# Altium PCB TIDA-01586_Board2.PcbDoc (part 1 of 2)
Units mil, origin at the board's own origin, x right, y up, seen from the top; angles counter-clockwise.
Board outline 2300 x 1600 mil, 4 copper layers (Layer 1 - Top Layer, Layer 2 - PWR, Layer 3 - GND, Layer 4 - Bottom Layer), stack 61.634 mil thick; 117 components, 50 nets, 280 pads, 152 vias.
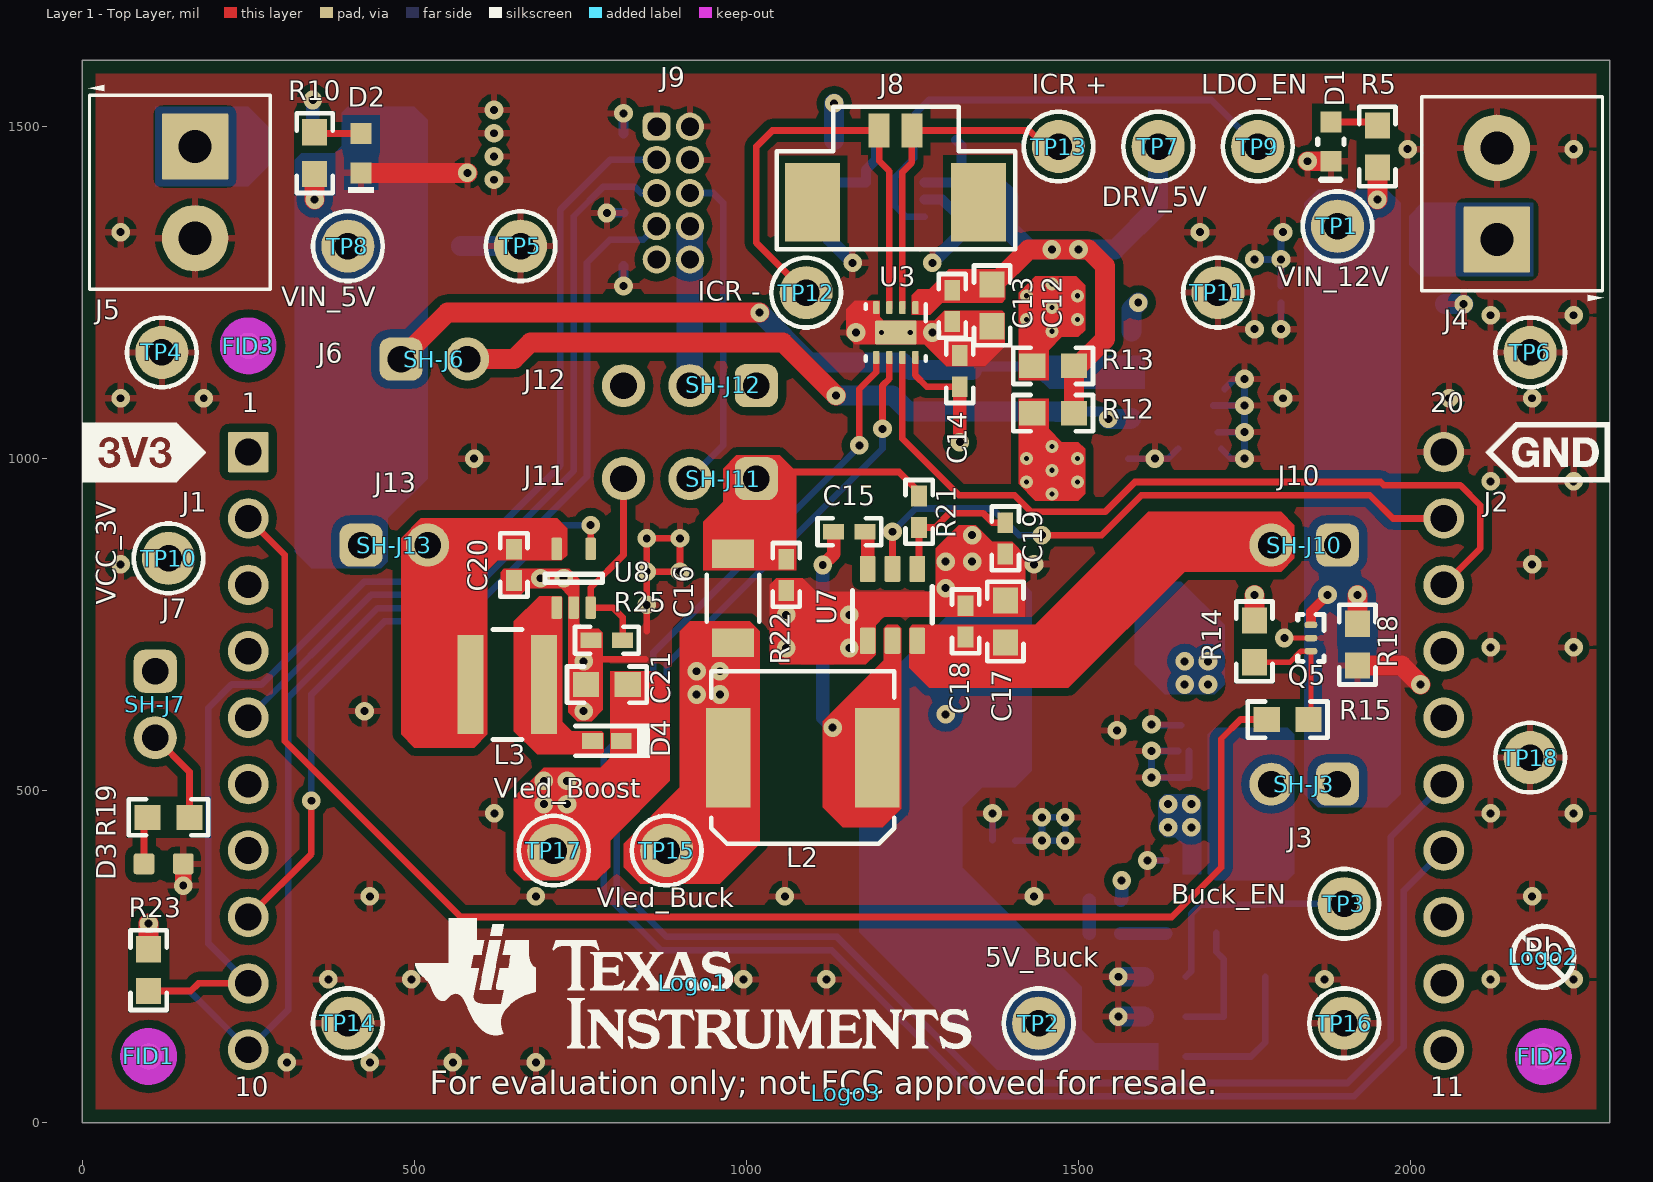
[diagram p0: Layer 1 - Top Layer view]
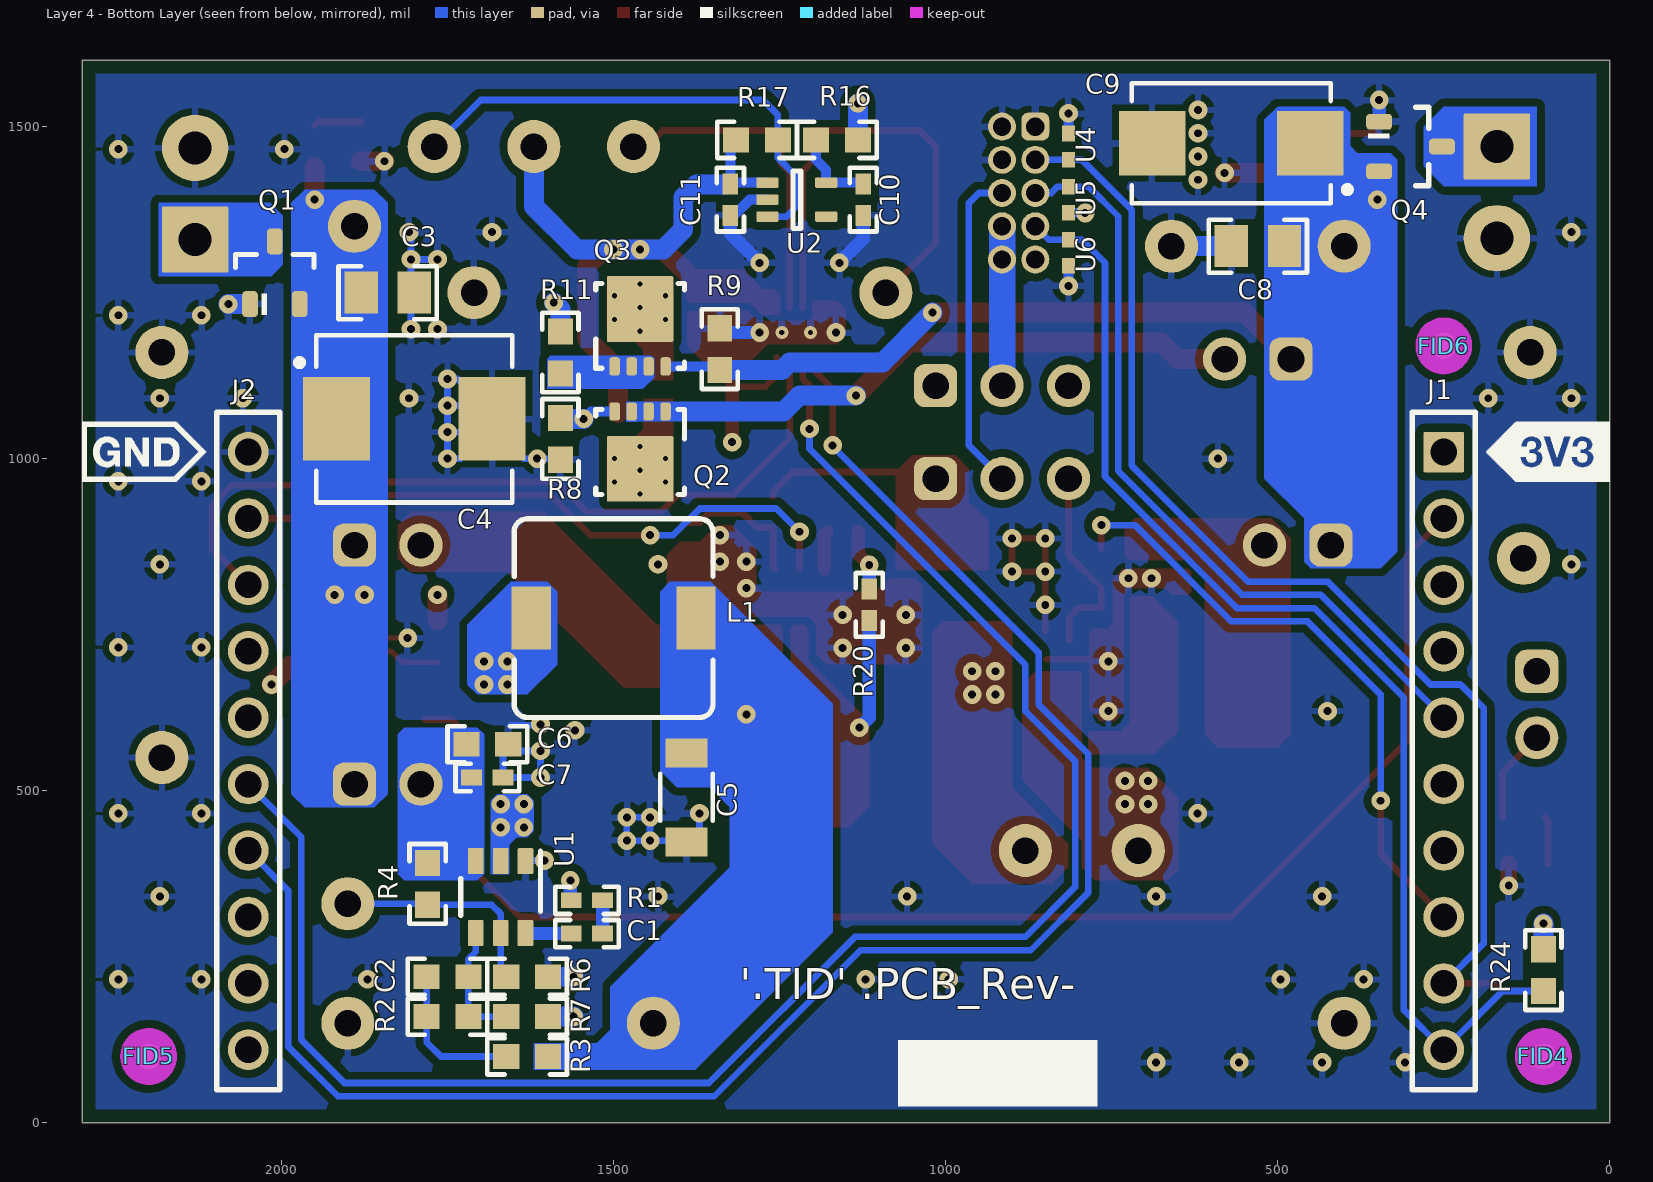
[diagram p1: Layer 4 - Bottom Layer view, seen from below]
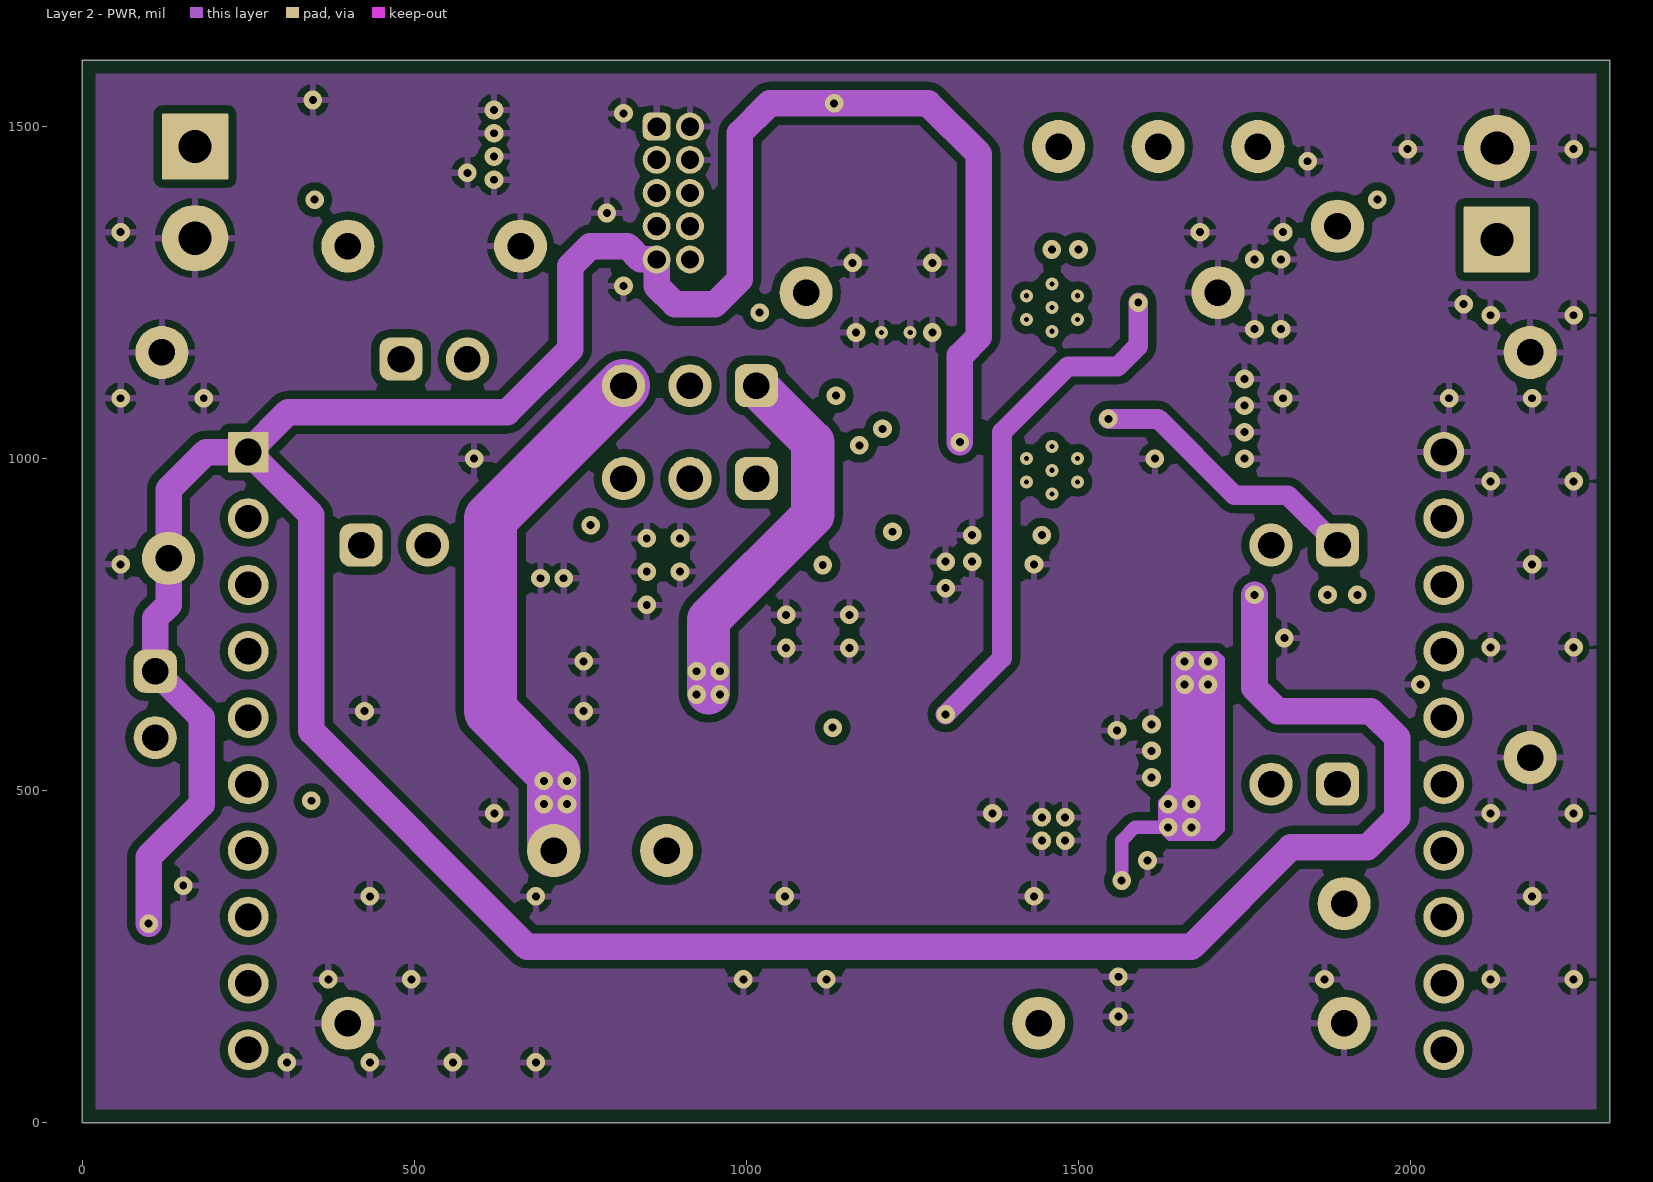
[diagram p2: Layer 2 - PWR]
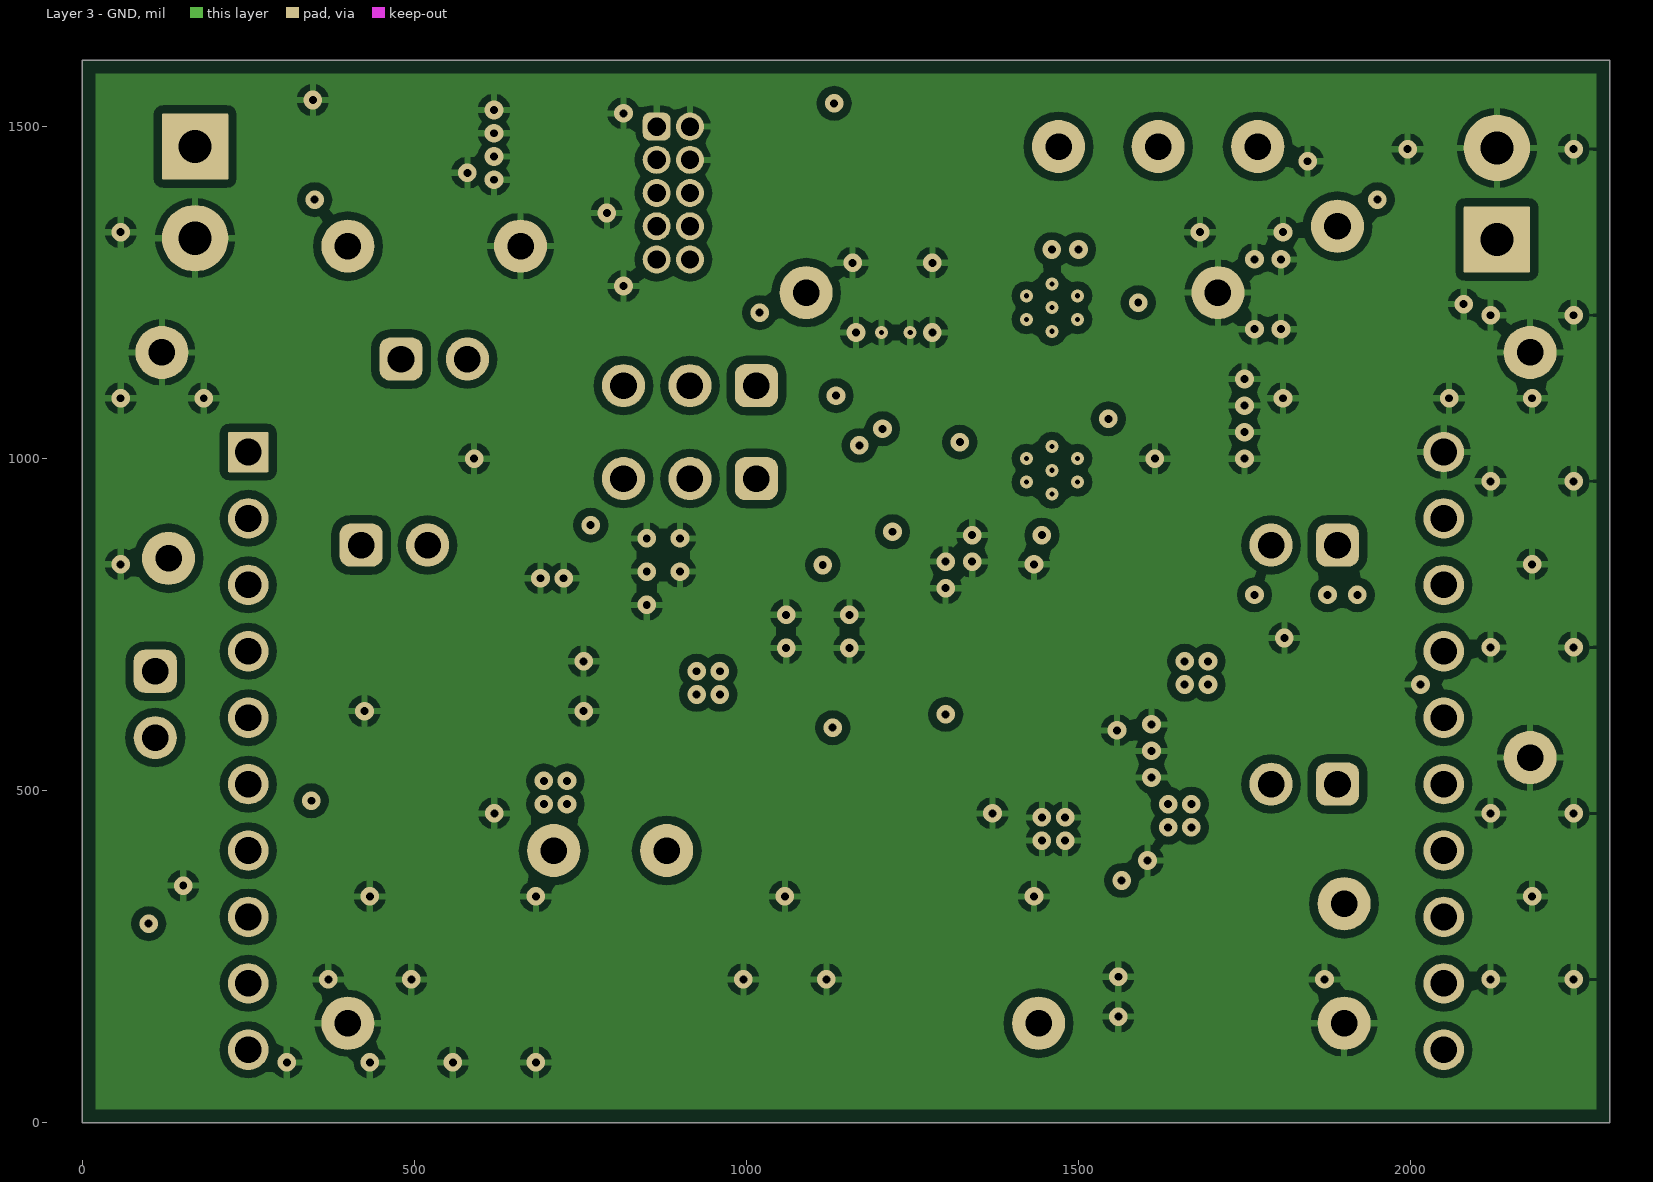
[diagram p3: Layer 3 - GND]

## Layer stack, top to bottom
Top Solder: solder mask 0.4, Solder Resist, Dk 3.5
Layer 1 - Top Layer: signal copper 1.4
Dielectric 1: prepreg 7, FR-4, Dk 4.2
Layer 2 - PWR: signal copper 1.417
Dielectric 2: core 42, FR-4, Dk 4.8
Layer 3 - GND: signal copper 1.417
Dielectric 3: prepreg 7, FR-4, Dk 4.2
Layer 4 - Bottom Layer: signal copper 1.4
Bottom Solder: solder mask 0.4, Solder Resist, Dk 3.5

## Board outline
0,0 0,1600 2300,1600 2300,0

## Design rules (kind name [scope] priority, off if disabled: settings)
AcuteAngle [All] p1: minimum=4.50000000000000E+0001 checktracksonly=FALSE
AssemblyTestPointUsage [All] p1: valid=2
BoardOutlineClearance BoardOutlineClearance_MountingHoles [OnCopper and InComponentClass('Mounting Holes')] p1: gap=40
BoardOutlineClearance BoardOutlineClearance_Poly [OnCopper and IsPoly] p2: gap=20
BoardOutlineClearance [OnCopper and Not InComponentClass('Logo') and not InComponentClass('FiducialMark') and not InRegion(1000,500,4000,800) and not InPoly] p3: gap=35
Clearance Clearance_Keepouts [((IsTrack Or IsArc) And Not InPoly) And IsFree and IsKeepOut vs ((IsTrack Or IsArc) And Not InPoly) And IsFree and IsKeepOut] p1: gap=0
Clearance Clearance_Poly [InPolygon] p2: gap=12
Clearance Clearance_FiducialMark [IsKeepOut and InComponentClass('FiducialMark') vs IsPad and InComponentClass('FiducialMark')] p3: gap=0
Clearance [All] p4: gap=7.87
ComponentClearance ComponentClearance_MountingHoles_FiducialMarks [InComponentClass('Mounting Holes') vs InComponentClass('FiducialMark')] p1: gap=50 collisioncheckmode=3 verticalgap=10 showdistances=FALSE
ComponentClearance ComponentClearance_Shunt [InComponentClass('Header') vs InComponentClass('Shunt')] p2: gap=0 collisioncheckmode=3 verticalgap=0 showdistances=FALSE
ComponentClearance ComponentClearance_Logo [InComponentClass('Logo')] p3: gap=10 collisioncheckmode=3 verticalgap=10 showdistances=TRUE
ComponentClearance ComponentClearance_ScrewToNut [(HasFootprint('NY PMS 440 0025 PH')) vs (HasFootprint('Keystone_1902C'))] p4: gap=5 collisioncheckmode=3 verticalgap=10 showdistances=TRUE
ComponentClearance ComponentClearance_MountingHoles [InComponentClass('Mounting Holes')] p5: gap=250 collisioncheckmode=3 verticalgap=100000 showdistances=TRUE
ComponentClearance ComponentClearance_SmallPassives [HasFootprint('0201*') or HasFootprint('0402*') or HasFootprint('0508') or HasFootprint('0603*') or HasFootprint('0612') or HasFootprint('0805*') or HasFootprint('0815*') or HasFootprint('0830*') or HasFootprint('1206*') or HasFootprint('1210*') or HasFootprint('1808*') or HasFootprint('1812*') or HasFootprint('1825*') or HasFootprint('2010*') or HasFootprint('2220*') or HasFootprint('2225*') or HasFootprint('2512*') or HasFootprint('2728*') or HasFootprint('3518*') vs HasFootprint('0201*') or HasFootprint('0402*') or HasFootprint('0508') or HasFootprint('0603*') or HasFootprint('0612') or HasFootprint('0805*') or HasFootprint('0815*') or HasFootprint('0830*') or HasFootprint('1206*') or HasFootprint('1210*') or HasFootprint('1808*') or HasFootprint('1812*') or HasFootprint('1825*') or HasFootprint('2010*') or HasFootprint('2220*') or HasFootprint('2225*') or HasFootprint('2512*') or HasFootprint('2728*') or HasFootprint('3518*')] p6: gap=10 collisioncheckmode=3 verticalgap=10 showdistances=TRUE
ComponentClearance ComponentClearance_THtoSMT [IsThruComponent vs IsSMTComponent] p7: gap=20 collisioncheckmode=3 verticalgap=30 showdistances=TRUE
ComponentClearance ComponentClearance_THtoTH [IsThruComponent vs IsThruComponent] p8: gap=30 collisioncheckmode=3 verticalgap=30 showdistances=TRUE
ComponentClearance [All] p9: gap=30 collisioncheckmode=3 verticalgap=10 showdistances=FALSE
DiffPairsRouting [All] p1: maxlimit=100 minlimit=10 mostfreqgap=10 toplayer_minwidth=15 toplayer_maxwidth=15 toplayer_prefwidth=15 midlayer1_minwidth=15 midlayer1_maxwidth=15 midlayer1_prefwidth=15 midlayer2_minwidth=15 midlayer2_maxwidth=15 midlayer2_prefwidth=15 bottomlayer_minwidth=15 bottomlayer_maxwidth=15 bottomlayer_prefwidth=15 maxuncoupledlength=1000
FabricationTestPointUsage TestPointUsage [All] p1: valid=2 allowmultiple=FALSE
FabricationTestpoint Testpoint [All] p1: side=3 testpointundercomponent=TRUE minsize=40 maxsize=100 preferedsize=60 minholesize=0 maxholesize=40 preferedholesize=32 testpointgrid=1 allowsidetop=TRUE allowsidebottom=TRUE usegrid=TRUE gridtolerance=0.01
FanoutControl Fanout_LCC [IsLCC] p1: bgadir=Out bgaviamode=Centered fanoutstyle=Auto fanoutdirection=Alternating viagrid=1 // Fanout_LCC (Default Rule)
FanoutControl Fanout_BGA [IsBGA] p2: bgadir=Out bgaviamode=Centered fanoutstyle=Auto fanoutdirection=Alternating viagrid=1 // Fanout_BGA (Default Rule)
FanoutControl Fanout_Default [All] p4: bgadir=Out bgaviamode=Centered fanoutstyle=Auto fanoutdirection=Alternating viagrid=1 // Fanout_Default (Default Rule)
FanoutControl Fanout_Small [(CompPinCount < 5)] p5: bgadir=Out bgaviamode=Centered fanoutstyle=Auto fanoutdirection=OutThenIn viagrid=1 // Fanout_Small (Default Rule)
HoleSize [All] p1: absolutevalues=TRUE maxlimit=251 minlimit=7.87 maxpercent=80.000 minpercent=20.000
MinimumAnnularRing MinimumAnnularRing_ThermalPadVias [IsVia and InAnyComponent] p1: minimumring=5.91
MinimumAnnularRing [All] p2: minimumring=5
MinimumSolderMaskSliver MinimumSolderMaskSliver_Logo [InComponentClass('Logo') vs InComponentClass('Logo')] p1: minsoldermaskwidth=0.7
MinimumSolderMaskSliver [All] p2: minsoldermaskwidth=3.94
PlaneConnect [All] p1: planeconnectstyle=Relief reliefexpansion=10 reliefentries=4 reliefconductorwidth=10 reliefairgap=10
PolygonConnect [All] p1: connectstyle=Relief reliefconductorwidth=10 reliefentries=4 polygonreliefangle="90 Angle" airgapwidth=10
RoutingVias ThermalPadVias [IsVia and InAnyComponent] p1: holewidth=7.87 width=19.68 viastyle="Through Hole" minholewidth=7.87 minwidth=19.68 maxholewidth=12.99 maxwidth=23.62
RoutingVias [All] p2: holewidth=16 width=34 viastyle="Through Hole" minholewidth=7.87 minwidth=26 maxholewidth=40 maxwidth=65
SilkToBoardRegionClearance [Not ((IsComment or IsDesignator) And (Hide <> 'False')) and not InRegion(1000,500,4000,800)] p1:
SilkToSilkClearance SilkToSilkClearance_Pb-FreeLogo [(HasFootprint('Pb-Free_Overlay_Medium') OR HasFootprint('Pb-Free_Overlay_Small')) vs (HasFootprint('Pb-Free_Overlay_Medium') OR HasFootprint('Pb-Free_Overlay_Small'))] p1: silktosilkclearance=0
SilkToSilkClearance [All] p2: silktosilkclearance=4
SilkToSolderMaskClearance SilkToComponentPadClearance [(IsPad or IsFill or IsRegion) and InAnycomponent] p1: minsilkscreentomaskgap=3.8 clearancetoexposedcopper=TRUE
SilkToSolderMaskClearance "Silk to Solder Mask Opening" [All] p2: minsilkscreentomaskgap=5 clearancetoexposedcopper=FALSE
SolderMaskExpansion [All] p1: expansion=1.97
Width [All] p1: maxlimit=100 minlimit=6 preferedwidth=10 checkconnectedcopper=TRUE
15 further rules are at their usual default settings.

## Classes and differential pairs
component class Logo: Logo1
component class TIDA-01586_Board2_Hardware: FID1 FID2 FID3 FID4 FID5 FID6 Logo1 Logo2 Logo3 SH-J3 SH-J6 SH-J7 SH-J10 SH-J11 SH-J12 SH-J13 ZZ1 ZZ2 ZZ3 ZZ4
component class FiducialMark: FID1 FID2 FID3 FID4 FID5 FID6
component class AssemblyNote: ZZ1 ZZ2 ZZ3 ZZ4
component class Header: J3 J6 J7 J9 J10 J11 J12 J13
component class Shunt: SH-J3 SH-J6 SH-J7 SH-J10 SH-J11 SH-J12 SH-J13
component class TIDA-01586_Board2_MCU_Drivers: C12 C13 C14 C15 C16 C17 C18 C19 C20 C21 D4 J1 J2 J8 J9 J10 J11 J12 J13 L2 L3 R20 R21 R22 R23 R24 R25 TP12 TP13 TP14 TP15 TP16 TP17 TP18 U3 U4 U5 U6 U7 U8
component class TIDA-01586_Board2_Power: C1 C2 C3 C4 C5 C6 C7 C8 C9 C10 C11 D1 D2 D3 J3 J4 J5 J6 J7 L1 Q1 Q2 Q3 Q4 Q5 R1 R2 R3 R4 R5 R6 R7 R8 R9 R10 R11 R12 R13 R14 R15 R16 R17 R18 R19 TP1 TP2 TP3 TP4 TP5 TP6 TP7 TP8 TP9 TP10 TP11 U1 U2

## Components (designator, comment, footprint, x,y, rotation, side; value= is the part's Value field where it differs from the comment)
C1 "GRM155R71A104KA01D" 0402 1540,285 r180 bottom
C2 "GRM1885C1H101JA01D" 0603 1750,220 r180 bottom
C3 "C0805C105K3RACTU" 0805_HV 1840,1250 r180 bottom
C4 "TPSV107K025R0100" 7361-38 1800,1060 r180 bottom
C5 "GRT31CR61A476KE13L" 1206_180 1390,490 r270 bottom
C6 "GRM188R61E106MA73D" 0603 1690,570 r180 bottom
C7 "C1005X7R1H104K050BB" 0402 1690,520 r180 bottom
C8 "C0805C105K3RACTU" 0805_HV 530,1320 r180 bottom
C9 "TPSD107K010R0100" 7343-31 570,1475 r0 bottom
C10 "GRM155R61A105ME15D" 0402 1124.09,1390 r90 bottom
C11 "GRM155R61A105ME15D" 0402 1324.09,1390 r270 bottom
C12 "GRM188R61E106MA73D" 0603 1370,1231 r270 top
C13 "GRM155R71A104KA01D" 0402 1310,1230 r270 top
C14 "GRM155R71A104KA01D" 0402 1321.32,1131.95 r90 top
C15 "GRM155R71A104KA01D" 0402 1155,890 r180 top
C16 "C3216X5R1E336M160AC" 1206_180 980,790 r90 top
C17 "GRM188R61E106MA73D" 0603 1390,755 r90 top
C18 "C1005X7R1H104K050BB" 0402 1330,755 r90 top
C19 "GRM155R71A823KA01D" 0402 1390,880 r270 top
C20 "CL05A106MP5NUNC" 0402 650,840 r270 top
C21 "GRM188R6YA475KE15D" 0603 790,660 r180 top
D1 "LS L29K-G1J2-1-Z" "LS L29K_Red" 1880,1477.38 r270 top
D2 "LB Q39G-L2N2-35-1" "LB Q39G_BLUE" 420,1460 r270 top
D3 "LP L296-J2L2-25" LPL296_Green 122.62,390 r0 top
D4 "NSR0240V2T1G" SOD-523 790,575 r180 top
FID1 "Fiducial" Fiducial10-20 100,100 r0 top
FID2 "Fiducial" Fiducial10-20 2200,100 r0 top
FID3 "Fiducial" Fiducial10-20 250,1170 r0 top
FID4 "Fiducial" Fiducial10-20 100,100 r180 bottom
FID5 "Fiducial" Fiducial10-20 2200,100 r180 bottom
FID6 "Fiducial" Fiducial10-20 250,1170 r180 bottom
J1 "SSQ-110-03-F-S" BoosterPack_20pin_J1 250,560 r180 bottom
J2 "SSQ-110-03-F-S" BoosterPack_20pin_J2 2050,560 r180 bottom
J3 "TSW-102-07-G-S" TSW-102-07-G-S 1840,510 r180 top
J4 "ED555/2DS" TERM_BLK_ED555-2DS 2130,1330 r90 top
J5 "ED555/2DS" TERM_BLK_ED555-2DS 170,1470 r270 top
J6 "TSW-102-07-G-S" TSW-102-07-G-S 530,1150 r0 top
J7 "TSW-102-07-G-S" TSW-102-07-G-S 110,630 r270 top
J8 "53398-0271" 0533980271 1224.6,1440 r0 top
J9 "GRPB052VWVN-RC" CONN_GRPB052VWVN-RC 890,1400 r270 top
J10 "TSW-102-07-G-S" TSW-102-07-G-S 1840,870 r180 top
J11 "TSW-103-07-G-S" TSW-103-07-G-S 915,970 r180 top
J12 "TSW-103-07-G-S" TSW-103-07-G-S 915,1110 r180 top
J13 "TSW-102-07-G-S" TSW-102-07-G-S 470,870 r0 top
L1 "SRR0745A-220M" SRR0745A 1500,760 r180 bottom
L2 "ELL-6UH181M" ELL6UH 1085,550 r180 top
L3 "IFSC1515AHER4R7M01" IFSC1515AH 640,660 r0 top
Logo1 "Texas Instruments" TI_Stacked_Overlay_Small 920,210 r0 top
Logo2 "Pb-Free Symbol" Pb-Free_Overlay_Small 2200,250 r0 top
Logo3 "FCC disclaimer" FCC_disclaimer 1150,45 r0 top
Q1 "SI2343CDS-T1-GE3" SOT-23 2010,1280 r90 bottom
Q2 "CSD25402Q3A" DNH0008A 1460,1010 r270 bottom
Q3 "CSD25402Q3A" DNH0008A 1460,1200 r90 bottom
Q4 "SI2343CDS-T1-GE3" SOT-23 300,1470 r180 bottom
Q5 "CSD17585F5T" YJK0003A 1850,730 r270 top
R1 "RC0402JR-070RL" 0402 1540,335 r0 bottom
R2 "RC0603FR-07100KL" 0603 1750,160 r180 bottom
R3 "RC0603JR-070RL" 0603 1630,100 r0 bottom
R4 "RC0603FR-07154KL" 0603 1780,360 r270 bottom
R5 "CRCW06032K87FKEA" 0603 1950,1470 r270 top
R6 "RC0603FR-0719K6L" 0603 1630,220 r0 bottom
R7 "RC0603FR-0713K3L" 0603 1630,160 r0 bottom
R8 "RC0603JR-0747KL" 0603 1580,1030 r90 bottom
R9 "RC0603JR-0747KL" 0603 1340,1165 r270 bottom
R10 "CRCW0603590RFKEA" 0603 350,1460 r270 top
R11 "RC0603JR-070RL" 0603 1580,1160 r90 bottom
R12 "RC0603JR-070RL" 0603 1462,1068.54 r0 top
R13 "RC0603JR-070RL" 0603 1462,1139.84 r180 top
R14 "RC0603FR-0710KL" 0603 1765,725 r90 top
R15 "RC0603JR-070RL" 0603 1815,607.24 r180 top
R16 "RC0603JR-070RL" 0603 1163.58,1480 r180 bottom
R17 "RC0603JR-070RL" 0603 1284.09,1480 r180 bottom
R18 "RC0603JR-0747KL" 0603 1920,720 r270 top
R19 "CRCW0603487RFKEA" 0603 130,460 r0 top
R20 "RC0402JR-070RL" 0402 1115,780 r270 bottom
R21 "CRCW0402910RJNED" 0402 1260,920 r90 top
R22 "CRCW04027R87FKED" 0402 1060,825 r90 top
R23 "RC0603FR-0710KL" 0603 100,230 r90 top
R24 "RC0603FR-0710KL" 0603 100,230 r90 bottom
R25 "CRCW04027R87FKED" 0402 790,726.7 r0 top
SH-J3 "SNT-100-BK-G" SNT-100-BK-G 1840,510 r180 top
SH-J6 "SNT-100-BK-G" SNT-100-BK-G 530,1150 r180 top
SH-J7 "SNT-100-BK-G" SNT-100-BK-G 110,630 r90 top
SH-J10 "SNT-100-BK-G" SNT-100-BK-G 1840,870 r180 top
SH-J11 "SNT-100-BK-G" SNT-100-BK-G 965,970 r180 top
SH-J12 "SNT-100-BK-G" SNT-100-BK-G 965,1111.25 r180 top
SH-J13 "SNT-100-BK-G" SNT-100-BK-G 470,870 r180 top
TP1 "5000" Keystone5000 1890,1350 r90 top
TP2 "5000" Keystone5000 1440,150 r90 top
TP3 "5004" Keystone5004 1900,330 r90 top
TP4 "5001" Keystone5001 120,1160 r90 top
TP5 "5001" Keystone5001 660,1320 r90 top
TP6 "5001" Keystone5001 2180,1160 r90 top
TP7 "5002" Keystone5002 1620,1470 r0 top
TP8 "5000" Keystone5000 400,1320 r90 top
TP9 "5004" Keystone5004 1770,1470 r0 top
TP10 "5000" Keystone5000 130,850 r90 top
TP11 "5001" Keystone5001 1710,1250 r90 top
TP12 "5002" Keystone5002 1090,1250 r90 top
TP13 "5002" Keystone5002 1470,1470 r0 top
TP14 "5001" Keystone5001 400,150 r90 top
TP15 "5000" Keystone5000 880,410 r90 top
TP16 "5001" Keystone5001 1900,150 r90 top
TP17 "5000" Keystone5000 710,410 r90 top
TP18 "5001" Keystone5001 2180,550 r90 top
U1 "TPS54202DDCR" DDC0006A_N 1670,340 r270 bottom
U2 "TLV70033DCKR" DCK0005A_N 1224.09,1390 r180 bottom
U3 "DRV8837CDSG" DSG0008A 1225,1190 r270 top
U4 "TPD1E10B06DPYR" DPY0002A 815,1470 r90 bottom
U5 "TPD1E10B06DPYR" DPY0002A 815,1390 r270 bottom
U6 "TPD1E10B06DPYR" DPY0002A 815,1310 r270 bottom
U7 "TPS54201DDCR" DDC0006A_N 1220,780 r90 top
U8 "TPS61169DCKR" DCK0005A_N 740,820 r90 top
ZZ1 "This Assembly Note is for PCB labels only" AssemblyNoteLabel 100,2000 r0 top
ZZ2 "These assemblies are ESD sensitive, ESD precautions shall be observed." AssemblyNote 100,1900 r0 top
ZZ3 "These assemblies must be clean and free from flux and all contaminants. Use of no clean flux is not acceptable." AssemblyNote 100,1800 r0 top
ZZ4 "These assemblies must comply with workmanship standards IPC-A-610 Class 2, unless otherwise specified." AssemblyNote 100,1700 r0 top

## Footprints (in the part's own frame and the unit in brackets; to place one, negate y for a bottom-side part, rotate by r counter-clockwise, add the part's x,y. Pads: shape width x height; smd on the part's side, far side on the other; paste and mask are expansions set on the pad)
0402 [mm] "0402 from SM-752 data"
  rect 0.8x0.6 smd: 1(-0.6,0) 2(0.6,0)
  silkscreen extent -1.22,-0.52 1.22,0.52, body extent -0.55,-0.3 0.55,0.3, height 0.6
0603 [mm] "0603 from SM-752 data"
  rect 1x0.95 smd: 1(-0.8,0) 2(0.8,0)
  silkscreen extent -1.52,-0.69 1.52,0.69, body extent -0.87,-0.47 0.87,0.47, height 1
0805_HV [mil] "0805 with 30mil clearance between pads"
  rect 50x63 smd: 1(-40,0) 2(40,0)
  silkscreen extent -74,-40 74,40, body extent -43,-29 43,29, height 57
1206_180 [mm] "1206_180"
  rect 1.1x1.6 smd: 1(-1.7,0) 2(1.7,0)
  silkscreen extent -0.9,-1 0.9,1, body extent -1.75,-0.95 1.75,0.95, height 1.8
7343-31 [mm] "Medium Density based on Kemet T495 dimensions"
  rect 2.55x2.45 smd: 1(-3.025,0) 2(3.025,0)
  silkscreen extent -4.56,-2.3 3.8,2.3, body extent -3.8,-2.3 3.8,2.3, height 3.1
7361-38 [mm] "Medium density IPC based on AVX dimensions for TPS series"
  rect 2.55x3.2 smd: 1(-2.975,0) 2(2.975,0)
  silkscreen extent -4.51,-3.2 3.75,3.2, body extent -3.75,-3.15 3.75,3.15, height 3.8
0533980271 [mm] "Molex PicoBlade 2 pos from documents no. SD-53398-033 dated 2006-04-02"
  rect 0.8x1.3 smd: 1(-0.625,1.375) 2(0.625,1.375)
  rect 2.1x3 smd: 3(-3.175,-1.375) 4(3.175,-1.375)
  silkscreen extent -4.55,-3.17 4.57,2.29, body extent -3.86,-2.44 3.79,1.76, height 4.8
AssemblyNote [mil] "Assembly Note"
AssemblyNoteLabel [mil] "Assembly Note for PCB Labels"
BoosterPack_20pin_J1 [mm] "Receptacle, 2.54mm, 10x1, TH"
  rrect6% 1.55x1.55 hole 1.02: 1(0,11.43)
  round 1.55 hole 1.02: 2(0,8.89) 3(0,6.35) 4(0,3.81) 5(0,1.27) 6(0,-1.27) 7(0,-3.81) 8(0,-6.35) 9(0,-8.89) 10(0,-11.43)
  silkscreen extent -1.21,-12.95 6.35,12.95, body extent -1.21,-12.95 1.21,12.95, height 8.51
BoosterPack_20pin_J2 [mm] "Receptacle, 2.54mm, 10x1, TH"
  round 1.55 hole 1.02: 11(0,-11.43) 12(0,-8.89) 13(0,-6.35) 14(0,-3.81) 15(0,-1.27) 16(0,1.27) 17(0,3.81) 18(0,6.35) 19(0,8.89) 20(0,11.43)
  silkscreen extent -6.35,-12.95 1.21,12.95, body extent -1.21,-12.95 1.21,12.95, height 8.51
CONN_GRPB052VWVN-RC [mm] "SULLINS"
  rrect50% 1.07x1.07 hole 0.7: 1(-2.54,-0.635)
  round 1.07 hole 0.7: 2(-2.54,0.635) 3(-1.27,-0.635) 4(-1.27,0.635) 5(0,-0.635) 6(0,0.635) 7(1.27,-0.635) 8(1.27,0.635) 9(2.54,-0.635) 10(2.54,0.635)
  body extent -3.17,-1.7 3.17,1.7, height 4
DCK0005A_N [mm] "SOT353, 5-Leads, Body 2x1.3mm, Pitch 0.65mm, Lead Span 2.1mm, IPC Medium Density"
  rrect25% 0.85x0.4 smd: 1(-1.125,0.65) 2(-1.125,0) 3(-1.125,-0.65) 4(1.125,-0.65) 5(1.125,0.65)
  silkscreen extent -0.15,-1.1 0.15,1.1, body extent -1.14,-1 1.14,1, height 0.95
DDC0006A_N [mm]
  rrect17% 1x0.6 smd: 1(-1.375,0.95) 2(-1.375,0) 3(-1.375,-0.95) 4(1.375,-0.95) 5(1.375,0) 6(1.375,0.95)
  silkscreen extent -1.75,-1.52 0.7,1.53, body extent -1.43,-1.48 1.43,1.49, height 0.92
DNH0008A [mm] "8 pin VSONP, 0.65 mm pitch"
  rrect50% 0.7x0.4 smd paste-0.05 mask-0.05: 1(-1.55,0.975) 2(-1.55,0.325) 3(-1.55,-0.325) 4(-1.55,-0.975) 5(1.55,-0.975) 6(1.55,-0.325) 7(1.55,0.325) 8(1.55,0.975)
  rrect14% 0.705x1.125 on Bottom Paste: 9(-0.208,-0.663) 9(-0.208,0.662) 9(0.697,-0.663) 9(0.697,0.662)
  rrect6% 1.775x2.45 on Bottom Solder: 9(0.327,0)
  rrect4% 2.51x2.55 smd paste-1.5 mask-1.5: 9(0.645,0)
  rect 0.5x0.3 on Bottom Solder: 9(1.175,-0.975) 9(1.175,-0.325) 9(1.175,0.325) 9(1.175,0.975)
  silkscreen extent -1.62,-1.7 1.62,1.7, body extent -1.65,-1.65 1.65,1.66, height 0.91
DPY0002A [mm] "R-PX2SON-N2"
  rect 0.6x0.5 smd: 1(-0.5,0) 2(0.5,0)
  body extent -0.55,-0.35 0.55,0.35, height 0.4
DSG0008A [mm] "SON, 8-Leads, Body 2x2mm, Pitch 0.5mm, Thermal Pad 1.6x0.9mm, TI Recommended"
  rrect40% 0.5x0.25 smd: 1(-0.95,0.75) 2(-0.95,0.25) 3(-0.95,-0.25) 4(-0.95,-0.75) 5(0.95,-0.75) 6(0.95,-0.25) 7(0.95,0.25) 8(0.95,0.75)
  rrect14% 0.9x0.7 on Top Paste: 9(0,0.45) 9(0,-0.45)
  rrect11% 0.9x1.6 smd paste-0.45: 9(0,0)
  silkscreen extent -1.07,-1.15 1.07,1.15, body extent -1,-1 1,1, height 0.77
ELL6UH [mm] "Panasonic recommended land pattern"
  rect 1.7x3.8 smd: 1(-2.85,0) 2(2.85,0)
  silkscreen extent -3.5,-3.3 3.5,3.3, body extent -3.45,-3.25 3.45,3.25, height 5
FCC_disclaimer [mil]
Fiducial10-20 [mm]
  round 1 smd mask+0.5: 1(0,0)
  Layer 1 - Top Layer keep-out circle w1.178: c0,0 r0.5
IFSC1515AH [mm] "SMD, 2-Leads, Body 3.8x3.8mm"
  rect 1x3.8 smd: 1(-1.4,0) 2(1.4,0)
  silkscreen extent -0.55,-2.1 0.55,2.1, body extent -2,-2 2,2, height 1.9
Keystone5000 [mil] "For Keystone 500x miniature loop terminals"
  round 80 hole 40: 1(0,0)
  silkscreen extent -52,-52 52,52, body extent -49,-49 49,49, height 182
Keystone5001 [mil] "For Keystone 500x miniature loop terminals"
  round 80 hole 40: 1(0,0)
  silkscreen extent -52,-52 52,52, body extent -49,-49 49,49, height 182
Keystone5002 [mil] "For Keystone 500x miniature loop terminals"
  round 80 hole 40: 1(0,0)
  silkscreen extent -52,-52 52,52, body extent -49,-49 49,49, height 182
Keystone5004 [mil] "For Keystone 500x miniature loop terminals"
  round 80 hole 40: 1(0,0)
  silkscreen extent -52,-52 52,52, body extent -49,-49 49,49, height 182
"LB Q39G_BLUE" [mm] "OSRAM"
  rect 0.8x0.8 smd: 1(-0.75,0) 2(0.75,0)
  silkscreen extent 1.3,-0.5 1.52,0.5, body extent -0.85,-0.45 0.85,0.45, height 0.4
LPL296_Green [mm] "SMD, 2-Leads, Body 1.3x0.8mm"
  rrect25% 0.8x0.8 smd paste-1: 1(-0.75,0) 2(0.75,0)
  rrect17% 0.6x0.7 on Top Paste mask-1: ""(-0.8,0) ""(0.8,0)
  body extent -0.9,-0.45 0.9,0.45, height 0.67
"LS L29K_Red" [mm] "SMD, 2-Leads, Body 1.3x0.8mm"
  rect 0.8x0.8 smd paste-0.4: 1(-0.75,0) 2(0.75,0)
  silkscreen extent -0.1,-0.5 1.45,0.5, body extent -0.9,-0.45 0.9,0.45, height 0.67
Pb-Free_Overlay_Small [mil]
  silkscreen extent -46,-46 46,46
SNT-100-BK-G [mil] "Samtec STEP model"
  round 1 on Mech3: 0(0,0)
  body extent -100,-50 100,50, height 344
SOD-523 [mm] "NXP Semiconductor recommended land pattern, nominal STEP model"
  rect 0.8x0.6 smd paste-0.05: 1(-0.55,0) 2(0.55,0)
  silkscreen extent -1.65,-0.66 1.2,0.66, body extent -0.8,-0.4 0.8,0.4, height 0.72
SOT-23 [mm] "SOT23, 3-Leads, Body 2.9x1.3mm, Pitch 0.95mm, Lead Span 2.5mm, IPC Medium Density"
  rrect50% 1x0.6 smd: 1(-1.2,0.95) 2(-1.2,-0.95) 3(1.2,0)
  silkscreen extent -1.62,-1.5 0.7,1.5, body extent -1.16,-1.45 1.21,1.45, height 1
SRR0745A [mm] "BOURNS"
  rect 1.5x2.4 smd: 1(-3.15,0) 2(3.15,0)
  silkscreen extent -3.8,-3.8 3.8,3.8, body extent -3.75,-3.75 3.75,3.75, height 4.7
TERM_BLK_ED555-2DS [mil]
  rrect4% 100x100 hole 50: 1(0,0)
  round 100 hole 50: 2(138,0)
  silkscreen extent -93,-161 215,113, body extent -69,-150 207,106, height 323
TI_Stacked_Overlay_Small [mil]
  silkscreen extent -418,-98 418,98
TSW-102-07-G-S [mm] "Samtec 100mil, 1x2, 230 mil above insulator"
  rrect50% 1.65x1.65 hole 1.016: 1(-1.27,0)
  round 1.65 hole 1.016: 2(1.27,0)
  body extent -2.54,-1.27 2.54,1.27, height 8.38
TSW-103-07-G-S [mm] "Samtec 100mil, 1x3, 230 mil above insulator"
  rrect50% 1.65x1.65 hole 1.016: 1(-2.54,0)
  round 1.65 hole 1.016: 2(0,0) 3(2.54,0)
  body extent -3.81,-1.27 3.81,1.27, height 8.38
YJK0003A [mm] "SMD, 3-Leads, Body 1.49x0.73mm"
  rrect50% 0.2x0.39 on Top Paste: 1(-0.525,0) 2(0,0) 3(0.525,0)
  rrect80% 0.25x0.49 smd paste-0.15 mask-0.05: 1(-0.5,0) 2(0,0) 3(0.5,0)
  silkscreen extent -0.9,-0.5 0.9,0.5, body extent -0.75,-0.37 0.74,0.36, height 0.35

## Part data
C1 C13 C14 C15: library part CMP-0006629-2, "CAP, CERM, 0.1 uF, 10 V, +/- 10%, X7R, 0402"
C2: library part CMP-0007171-4, "CAP, CERM, 100 pF, 50 V, +/- 5%, C0G/NP0, 0603"
C3 C8: library part CMP-0007728-2, "CAP, CERM, 1 uF, 25 V, +/- 10%, X7R, 0805"
C4: library part CMP-0012041-2, "CAP, TA, 100 uF, 25 V, +/- 10%, 0.1 ohm, SMD"
C5: library part CMP-0009013-2, "CAP, CERM, 47 uF, 10 V, +/- 10%, X5R, AEC-Q200 Grade 1, 1206"
C6 C12 C17: library part CMP-0007344-5, "CAP, CERM, 10 uF, 25 V, +/- 20%, X5R, 0603"
C7 C18: library part CMP-0006297-2, "CAP, CERM, 0.1 uF, 50 V, +/- 10%, X7R, 0402"
C9: library part CMP-0011859-2, "CAP, TA, 100 uF, 10 V, +/- 10%, 0.1 ohm, SMD"
C10 C11: library part CMP-0064927-2, "CAP, CERM, 1 uF, 10 V,+/- 20%, X5R, 0402"
C16: library part CMP-0008655-2, "CAP, CERM, 33 uF, 25 V, +/- 20%, X5R, 1206"
C19: library part CMP-0006637-2, "CAP, CERM, 0.082 uF, 10 V, +/- 10%, X7R, 0402"
C20: library part CMP-0006339-2, "CAP, CERM, 10 uF, 10 V, +/- 20%, X5R, 0402"
C21: library part CMP-0007357-5, "CAP, CERM, 4.7 uF, 35 V, +/- 10%, X5R, 0603"
D1: library part CMP-0002902-1, "LED, Red, SMD"
D2: library part CMP-0002849-1, "LED, Blue, SMD"
D3: library part CMP-0077694-1, "LED, Green, SMD"
D4: library part CMP-0028616-2, "Diode, Schottky, 40 V, 0.25 A, SOD-523"
FID1 FID2 FID3: library part CMP-0077181-1, "Fiducial mark.  There is nothing to buy or mount."
FID4 FID5 FID6: "Fiducial mark.  There is nothing to buy or mount."
J1: library part CMP-0003839-1, "Receptacle, 2.54mm, 10x1, Gold, TH"
J2: library part CMP-0078267-1, "Receptacle, 2.54mm, 10x1, Gold, TH"
J3 J6 J7 J10 J13: library part CMP-0075405-2, "Header, 100mil, 2x1, Gold, TH"
J4 J5: library part CMP-0074913-1, "Terminal Block, 3.5mm Pitch, 2x1, TH"
J8: library part CMP-0055117-1, "Plug, SMT, Vertical, 1.25mm, 1x2"
J9: library part CMP-0002340-2, "Header, 50mil, 5x2, Gold, TH"
J11 J12: library part CMP-0075407-2, "Header, 100mil, 3x1, Gold, TH"
L1: library part CMP-0057729-2, "Inductor, Shielded Drum Core, Ferrite, 22 uH, 1.65 A, 0.096 ohm, AEC-Q200 Grade 1, SMD"
L2: library part CMP-0060108-1, "Inductor, Shielded Drum Core, Ferrite, 180 uH, 0.47 A, 0.75 ohm, SMD"
L3: library part CMP-0063230-1, "Inductor, Shielded, Ferrite, 4.7 uH, 2 A, 0.09 ohm, SMD"
Logo1: library part CMP-0074838-1, "Texas Instrument Corporate Signature"
Logo2: library part CMP-0074839-1
Logo3: library part CMP-0074847-1, "FCC_disclaimer"
Q1 Q4: library part CMP-0000096-2, "MOSFET, P-CH, -30 V, -5.9 A, SOT-23"
Q2 Q3: library part CMP-0000025-2, "MOSFET, P-CH, -20 V, -15 A, DNH0008A (VSONP-8)"
Q5: library part CMP-0067551-1, "MOSFET, N-CH, 30 V, 5.9 A, YJK0003A (PICOSTAR-3)"
R1 R20: library part CMP-0027004-2, "RES, 0, 5%, 0.063 W, 0402"
R2: library part CMP-0022735-3, "RES, 100 k, 1%, 0.1 W, 0603"
R3 R11 R12 R13 R15 R16 R17: library part CMP-0025885-3, "RES, 0, 5%, 0.1 W, 0603"
R4: library part CMP-0022810-2, "RES, 154 k, 1%, 0.1 W, 0603"
R5: library part CMP-0022283-4, "RES, 2.87 k, 1%, 0.1 W, AEC-Q200 Grade 0, 0603"
R6: library part CMP-0022861-3, "RES, 19.6 k, 1%, 0.1 W, 0603"
R7: library part CMP-0022790-3, "RES, 13.3 k, 1%, 0.1 W, 0603"
R8 R9 R18: library part CMP-0025925-3, "RES, 47 k, 5%, 0.1 W, 0603"
R10: library part CMP-0022506-5, "RES, 590, 1%, 0.1 W, AEC-Q200 Grade 0, 0603"
R14 R23 R24: library part CMP-0022746-3, "RES, 10.0 k, 1%, 0.1 W, 0603"
R19: library part CMP-0022442-5, "RES, 487, 1%, 0.1 W, AEC-Q200 Grade 0, 0603"
R21: library part CMP-0026986-3, "RES, 910, 5%, 0.063 W, AEC-Q200 Grade 0, 0402"
R22 R25: library part CMP-0026567-2, "RES, 7.87, 1%, 0.063 W, AEC-Q200 Grade 0, 0402"
SH-J3 SH-J6 SH-J7 SH-J10 SH-J11 SH-J12 SH-J13: library part CMP-0003623-1, "Shunt, 100mil, Gold plated, Black"
TP1 TP2 TP8 TP10 TP15 TP17: library part CMP-0055137-1, "Test Point, Miniature, Red, TH"
TP3 TP9: library part CMP-0055141-1, "Test Point, Miniature, Yellow, TH"
TP4 TP5 TP6 TP11 TP14 TP16 TP18: library part CMP-0055138-1, "Test Point, Miniature, Black, TH"
TP7 TP12 TP13: library part CMP-0055139-1, "Test Point, Miniature, White, TH"
U1: library part CMP-0073969-2, "4.5V to 28V Input, 2A Output, EMI Friendly Synchronous Step-Down Converter, DDC0006A (SOT-23-T-6)"
U2: library part CMP-0035682-1, "Single Output LDO, 200 mA, Fixed 3.3 V Output, 2 to 5.5 V Input, with Low IQ, 5-pin SC70 (DCK), -40 to 125 degC, Green (RoHS & no Sb/Br)"
U3: library part CMP-0013449-3, "1-A Low-Voltage H-Bridge Driver, DSG0008A (WSON-8)"
U4 U5 U6: library part CMP-0043093-1, "ESD in 0402 Package with 10 pF Capacitance and 6 V Breakdown, 1 Channel, -40 to +125 degC, 2-pin X2SON (DPY), Green (RoHS & no Sb/Br)"
U7: library part CMP-0013279-3, "4.5V TO 28V INPUT VOLTAGE, 1.5A OUTPUT CURRENT, SYNCHRONOUS BUCK WLED Driver, DDC0006A (SOT-6)"
U8: library part CMP-0073719-1, "TPS61169 38-V High-Current Boost WLED Driver, DCK0005A (SOT-SC70-5)"
ZZ1: library part CMP-0003616-3
ZZ2: library part CMP-0077236-1
ZZ3: library part CMP-0077237-1
ZZ4: library part CMP-0077238-1

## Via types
v1: diameter 28, hole 12, Layer 1 - Top Layer to Layer 4 - Bottom Layer, tented both sides, 136 vias
v2: diameter 19.68, hole 7.87, Layer 1 - Top Layer to Layer 4 - Bottom Layer, tented both sides, 16 vias

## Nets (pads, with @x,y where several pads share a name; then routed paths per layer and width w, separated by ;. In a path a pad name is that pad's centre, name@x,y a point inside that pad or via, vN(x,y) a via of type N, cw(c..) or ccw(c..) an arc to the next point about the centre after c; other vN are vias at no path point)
5v_buck: C5.1 L1.2 R3.1 R11.2 TP2.1 | length 831.7
  Layer 2 - PWR w30: v1(1300,615) 1385,700 1385,1040 1483.98,1138.98 1558.98,1138.98 1590,1170 v1(1590,1235)
  Layer 4 - Bottom Layer w30: R11.2@1580,1191.5 1580,1225 v1(1590,1235)
CLOSE_ICR: J2.15 U3.6 | length 2699.7
  Layer 1 - Top Layer w10: v1(1205,1045) 1205,1110 1215.16,1120.16 U3.6@1215.16,1152.6
  Layer 4 - Bottom Layer w10: v1(1205,1045) 1205,1015 880,690 880,620 805,545 805,355 880,280 1136.61,280 1356.61,60 1905,60 1970,125 1970,430 J2.15@2050,510
DARK: J1.5 J9.5 U5.1 | length 1174.8
  Layer 4 - Bottom Layer w10: J1.5@250,610 435,795 553.28,795 740,981.72 740,1365 784.68,1409.68 U5.1@815,1409.68 831.32,1409.68 841,1400 J9.5@865,1400
DRV_5V: C11.1 C12.1 C13.1 R12.2 R13.1 R17.1 TP7.1 U2.1 U3.1 | length 1050
  Layer 1 - Top Layer w30: C12.1@1370,1261.5 1371.5,1261.5 1425,1315 v1(1460,1315) v1(1500,1315) 1515,1315 1540,1290 1540,1180 1499.84,1139.84 R13.1@1493.5,1139.84 R12.2@1493.5,1068.54
  Layer 4 - Bottom Layer w15: U2.1@1268.39,1415.59 1322.13,1415.59 C11.1@1324.09,1413.62 1324.09,1471.5 R17.1@1315.59,1480
  Layer 4 - Bottom Layer w30: C11.1@1329,1413 1375,1413 1395,1393 1395,1345 1425,1315 v1(1460,1315) v1(1500,1315) 1555,1315 1620,1380 TP7.1@1620,1470
fb_12v5v: C2.2 R2.2 R7.2 U1.4 | length 187.5
  Layer 4 - Bottom Layer w10: R7.2@1661.5,160 R2.2@1718.5,160 C2.2@1718.5,220 1718.5,246.5 1707.4,257.6 U1.4@1707.4,285.87
FB_ANA: J9.6 J11.2 | length 491.9
  Layer 4 - Bottom Layer w10: J11.2@915,970 965,1020 965,1385 950,1400 J9.6@915,1400
fb_led_boost: J11.3 R25.2 U8.3 | length 303.4
  Layer 1 - Top Layer w10: R25.2@813.62,726.7 813.62,761.38 799.29,775.71 U8.3@765.59,775.71 765.59,805.59 815,855 J11.3@815,970
fb_led_buck: C16.2 J11.1 R21.2 R22.2 | length 262.9
  Layer 1 - Top Layer w10: J11.1@1020,970 1030,980 1230,980 1260,950 R21.2@1260,943.62
fb_led_buck_filt: C19.1 R21.1 U7.4 | length 208.2
  Layer 1 - Top Layer w10: U7.4@1257.4,834.13 1260,836.73 R21.1@1260,896.38 1284.38,896.38 1306,918 1356.21,918 1370.59,903.62 C19.1@1390,903.62
GND: C3.2 C4.2 C5.2 C6.2 C7.2 C8.1 C9.2 C10.1 C11.2 C12.2 C13.2 C14.2 C17.2 C18.2 C19.2 C20.2 C21.2 D1.2 D2.2 D3.2 J2.20 J4.2 J5.2 J9.1 J9.2 J9.4 Q1.1 Q4.1 Q5.2@1850,730 R6.1 R7.1 R8.1 R9.1 R18.2 R22.1 R25.1 TP4.1 TP5.1 TP6.1 TP11.1 TP14.1 TP16.1 TP18.1 U1.1 U2.2 U3.4 U3.9@1225,1190 U4.2 U5.2 U6.2 U7.1 U8.2 | length 2392
  Layer 1 - Top Layer w8: v1(1810,730) Q5.2@1850,730
  Layer 1 - Top Layer w10: v1(755,695) 758,698 848,698 ; 850,740 v1(850,780) v1(850,830) ; v1(850,830) v1(850,880) v1(900,880) v1(900,830) v1(850,830)
  Layer 1 - Top Layer w25: v1(152.15,357.15) D3.2@152.15,390
  Layer 1 - Top Layer w30: D2.2@420,1430.47 v1(580,1430.47) ; v1(1845,1447.85) D1.2@1880,1447.85 ; R18.2@1920,688.5 1986.5,688.5 v1(2015,660)
  Layer 4 - Bottom Layer w10: C5.2@1370.5,426 v1(1370.5,466) ; C5.2@1405,425 v1(1445,425) ; v1(1445,460) v1@1485,460 ; v1@1445,465 v1(1445,425) ; v1@1480,420 v1(1480,460) ; v1@1485,425 v1(1445,425) ; R8.1@1575,1000 v1(1615,1000) 1635,1000 C4.2@1650,1015 ; v1(1604,395) U1.1@1632.6,395 ; v1@1610,598.9 1655,598.9 ; C6.2@1650,560 v1(1610,560) v1(1610,520) C7.2@1666.38,520 C6.2@1666.38,560 ; C4.2@1702.87,1080 v1(1750,1080) ; C4.2@1710,1040 v1(1750,1040) ; C4.2@1715,1015 1730,1000 v1(1750,1000) v1(1750,1040) ; C4.2@1720,1105 1735,1120 v1(1750,1120) v1(1750,1080) ; v1(1765,1300) v1(1805,1300) ; v1(1805,1195) C3.2@1805,1235 ; C3.2@1805,1260 v1(1805,1300) ; v1@1805,1340 v1(1805,1300) ; v1(1750,1040) v1(1750,1080)
  Layer 4 - Bottom Layer w15: v1@790,1370.32 U5.2@815,1370.32 ; v1(815,1260) U6.2@815,1290.32 ; U4.2@815,1489.68 v1(815,1520) ; U2.2@1268.39,1390 1295,1390 1318.62,1366.38 C11.2@1324.09,1366.38
  Layer 4 - Bottom Layer w20: Q4.1@347.24,1507.4 v1(347.24,1540) ; C10.1@1124.09,1366.38 1124.09,1330.91 v1(1160,1295) ; v1(1280,1190) 1333.5,1190 R9.1@1340,1196.5 ; v1(1280,1295) 1324.09,1339.09 C11.2@1324.09,1366.38
  Layer 4 - Bottom Layer w30: C8.1@570,1320 TP5.1@660,1320 ; v1(1560,160) R7.1@1598.5,160 ; v1(1560,220) R6.1@1598.5,220 ; Q1.1@2052,1232.76 v1(2080,1232.76)
  other v1: 308,91 433,91 558,91 683,91 370.5,216 495.5,216 995.5,216 1120.5,216 1870.5,216 2120.5,216 2245.5,216 433,341 683,341 1058,341 1433,341 2183,341 1480,425 620.5,466 2120.5,466 2245.5,466 1558,591 1610,600 425,620 755,620 1060,715 1155,715 2120.5,716 2245.5,716 1060,765 1155,765 1300,805 690,820 725,820 58,841 1433,841 2183,841 1300,845 1340,845 1340,885 2120.5,966 2245.5,966 590,1000 58,1091 183,1091 1808,1091 2058,1091 2183,1091 1165,1190 1765,1195 2120.5,1216 2245.5,1216 58,1341 1683,1341 1808,1341 790,1370 620,1420 620,1455 1995.5,1466 2245.5,1466 620,1490 620,1525
  other v2: 1203.35,1190 1246.65,1190
ICR_neg: J8.1 TP12.1 U3.3 | length 719.1
  Layer 1 - Top Layer w10: TP12.1@1090,1250 1015,1325 1015,1470 1039.13,1494.13 J8.1@1199.99,1494.13 1199.99,1448.16 1215.16,1432.99 U3.3@1215.16,1227.4
ICR_pos: J8.2 TP13.1 U3.2 | length 503.5
  Layer 1 - Top Layer w10: U3.2@1234.84,1227.4 1234.84,1431.84 1249.21,1446.21 J8.2@1249.21,1494.13 1425.87,1494.13 1450,1470 TP13.1@1470,1470
ldo_3v: C10.2 R16.1 U2.5 | length 127.3
  Layer 4 - Bottom Layer w15: C10.2@1124.09,1413.62 1126.06,1415.59 U2.5@1179.8,1415.59 1179.8,1434.8 1195.07,1450.07 R16.1@1195.07,1480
